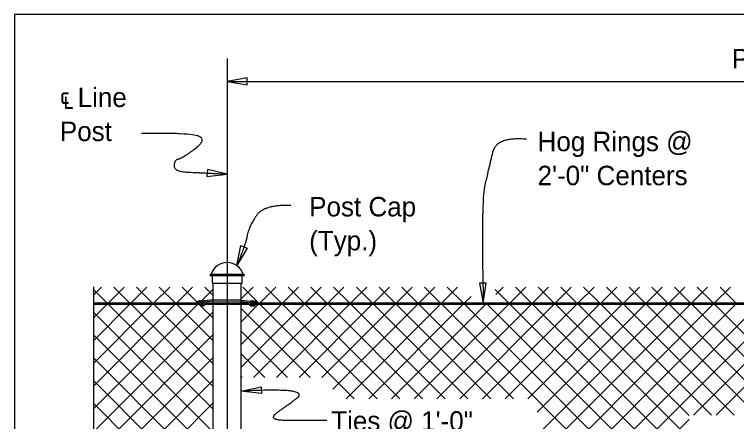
# Model space of a CAD drawing. Extents: x 0 to 72.1, y -7 to 30.
# Drawn here: x 0.02 to 7.5, y 23.8 to 28.01 of the extents above; entities that cross this region are included whole.
import ezdxf

# ---------------------------------------------------------------- set-up
doc = ezdxf.new("R2010")
doc.units = 0
for name, color, linetype in [('ActivePts-ConstElements', 7, 'Continuous'), ('AdhocPoint_dp', 7, 'Continuous'), ('Border', 7, 'Continuous'), ('Patterning', 7, 'Continuous'), ('PlotBorder_dp', 7, 'Continuous'), ('SheetBorder_dp', 7, 'Continuous'), ('TextStructures', 7, 'Continuous')]:
    doc.layers.add(name, color=color, linetype=linetype)

msp = doc.modelspace()

# ---------------------------------------------------------------- linework, layer by layer
at = {"layer": 'ActivePts-ConstElements'}
msp.add_lwpolyline([(0.016, 2.0538), (41.2266, 2.0538), (41.2266, 28.0138), (0.016, 28.0138)], close=True, dxfattribs=at)
at = {"layer": 'AdhocPoint_dp'}
for p, q in [((0.9187, 25.1899), (0.8352, 25.1065)), ((0.9779, 25.0233), (0.8352, 25.1659)), ((1.1544, 25.1899), (0.9877, 25.0233)), ((1.2136, 25.0233), (1.0469, 25.1899)), ((1.3901, 25.1899), (1.2234, 25.0233)), ((1.4493, 25.0233), (1.2826, 25.1899)), ((1.6258, 25.1899), (1.4591, 25.0233)), ((1.685, 25.0233), (1.5183, 25.1899)), ((1.8615, 25.1899), (1.6948, 25.0233)), ((1.9092, 25.0348), (1.754, 25.1899)), ((2.0763, 25.1691), (1.9541, 25.0468)), ((2.0763, 25.1033), (1.9897, 25.1899)), ((2.4906, 25.1899), (2.368, 25.0674)), ((2.5498, 25.0233), (2.3831, 25.1899)), ((2.7263, 25.1899), (2.5596, 25.0233)), ((2.7855, 25.0233), (2.6188, 25.1899)), ((2.962, 25.1899), (2.7953, 25.0233)), ((3.0212, 25.0233), (2.8545, 25.1899)), ((3.1977, 25.1899), (3.031, 25.0233)), ((3.2569, 25.0233), (3.0902, 25.1899)), ((3.4334, 25.1899), (3.2667, 25.0233)), ((3.4926, 25.0233), (3.3259, 25.1899)), ((3.6691, 25.1899), (3.5024, 25.0233)), ((3.7283, 25.0233), (3.5616, 25.1899)), ((3.9048, 25.1899), (3.7381, 25.0233)), ((3.964, 25.0233), (3.7973, 25.1899)), ((4.1405, 25.1899), (3.9738, 25.0233)), ((4.1997, 25.0233), (4.033, 25.1899)), ((4.3762, 25.1899), (4.2095, 25.0233)), ((4.4354, 25.0233), (4.2687, 25.1899)), ((4.6119, 25.1899), (4.4452, 25.0233)), ((4.6711, 25.0233), (4.5044, 25.1899)), ((5.1425, 25.0233), (5.0007, 25.1651)), ((5.0833, 25.1899), (5.0071, 25.1137)), ((5.319, 25.1899), (5.1523, 25.0233)), ((5.3782, 25.0233), (5.2116, 25.1899)), ((5.5547, 25.1899), (5.388, 25.0233)), ((5.6139, 25.0233), (5.4473, 25.1899)), ((5.7904, 25.1899), (5.6237, 25.0233)), ((5.8496, 25.0233), (5.683, 25.1899)), ((6.0261, 25.1899), (5.8594, 25.0233)), ((6.0853, 25.0233), (5.9187, 25.1899)), ((6.2618, 25.1899), (6.0951, 25.0233)), ((6.321, 25.0233), (6.1544, 25.1899)), ((6.4975, 25.1899), (6.3308, 25.0233)), ((6.5567, 25.0233), (6.3901, 25.1899)), ((6.7332, 25.1899), (6.5665, 25.0233)), ((6.7924, 25.0233), (6.6258, 25.1899)), ((6.9689, 25.1899), (6.8022, 25.0233)), ((7.0281, 25.0233), (6.8615, 25.1899)), ((7.2046, 25.1899), (7.0379, 25.0233)), ((7.2638, 25.0233), (7.0972, 25.1899)), ((7.4403, 25.1899), (7.2736, 25.0233)), ((7.4995, 25.0233), (7.3329, 25.1899)), ((4.7518, 25.0941), (4.6809, 25.0233)), ((1.9207, 25.0233), (1.9163, 25.0277)), ((4.9068, 25.0233), (4.9068, 25.0233)), ((1.9158, 25.0085), (0.8352, 23.928)), ((1.6801, 25.0085), (0.8352, 24.1637)), ((1.2087, 25.0085), (0.8352, 24.6351)), ((1.4444, 25.0085), (0.8352, 24.3994)), ((0.973, 25.0085), (0.8352, 24.8708)), ((2.0763, 23.9248), (0.9927, 25.0085)), ((2.0719, 24.165), (1.2284, 25.0085)), ((2.0763, 24.3962), (1.4641, 25.0085)), ((2.0763, 24.6319), (1.6998, 25.0085)), ((2.0763, 24.8676), (1.9469, 24.9971)), ((3.0163, 25.0085), (2.368, 24.3603)), ((2.7806, 25.0085), (2.368, 24.596)), ((2.5449, 25.0085), (2.368, 24.8317)), ((3.0842, 24.2532), (2.368, 24.9694)), ((3.252, 25.0085), (2.4966, 24.2532)), ((3.5404, 24.0327), (2.5645, 25.0085)), ((3.4877, 25.0085), (2.7323, 24.2532)), ((3.7761, 24.0327), (2.8002, 25.0085)), ((3.7234, 25.0085), (2.968, 24.2532)), ((4.0118, 24.0327), (3.0359, 25.0085)), ((3.9591, 25.0085), (3.2037, 24.2532)), ((4.2475, 24.0327), (3.2716, 25.0085)), ((4.1948, 25.0085), (3.319, 24.1328)), ((4.4305, 25.0085), (3.4546, 24.0327)), ((4.4832, 24.0327), (3.5073, 25.0085)), ((4.6662, 25.0085), (3.6903, 24.0327)), ((4.7189, 24.0327), (3.7431, 25.0085)), ((4.9019, 25.0085), (3.926, 24.0327)), ((4.9546, 24.0327), (3.9788, 25.0085)), ((5.1376, 25.0085), (4.1617, 24.0327)), ((5.1903, 24.0327), (4.2145, 25.0085)), ((7.2589, 25.0085), (4.2934, 22.043)), ((5.3733, 25.0085), (4.3974, 24.0327)), ((7.2652, 22.1934), (4.4502, 25.0085)), ((7.4946, 25.0085), (4.5291, 22.043)), ((5.609, 25.0085), (4.6331, 24.0327)), ((7.4194, 22.2749), (4.6859, 25.0085)), ((7.7303, 25.0085), (4.7648, 22.043)), ((5.8447, 25.0085), (4.8688, 24.0327)), ((7.5736, 22.3564), (4.9216, 25.0085)), ((7.966, 25.0085), (5.0005, 22.043)), ((6.0804, 25.0085), (5.1045, 24.0327)), ((7.7279, 22.4379), (5.1573, 25.0085)), ((6.3161, 25.0085), (5.3403, 24.0327)), ((7.0117, 23.3898), (5.393, 25.0085)), ((6.5518, 25.0085), (5.4365, 23.8932)), ((6.7875, 25.0085), (5.4365, 23.6575)), ((7.0232, 25.0085), (5.5838, 23.5691)), ((7.0117, 23.6255), (5.6287, 25.0085)), ((7.0117, 23.8612), (5.8644, 25.0085)), ((7.2437, 23.8649), (6.1001, 25.0085)), ((7.4794, 23.8649), (6.3358, 25.0085)), ((7.7151, 23.8649), (6.5715, 25.0085)), ((7.9508, 23.8649), (6.8072, 25.0085)), ((8.1865, 23.8649), (7.0429, 25.0085)), ((8.2017, 25.0085), (7.057, 23.8638)), ((8.4222, 23.8649), (7.2786, 25.0085)), ((8.4374, 25.0085), (7.2938, 23.8649)), ((2.0763, 24.9334), (0.8352, 23.6923)), ((2.0763, 23.6891), (0.8352, 24.9302)), ((2.8485, 24.2532), (2.368, 24.7337)), ((2.0763, 24.6977), (0.8352, 23.4566)), ((2.0763, 23.4534), (0.8352, 24.6945)), ((2.6128, 24.2532), (2.368, 24.4979)), ((2.0763, 24.462), (0.8142, 23.1998)), ((2.0763, 23.2177), (0.8352, 24.4588)), ((2.3771, 24.2532), (2.368, 24.2622)), ((2.0763, 24.2263), (0.8352, 22.9852)), ((2.0763, 22.982), (0.8352, 24.2231)), ((2.0763, 23.9906), (0.8352, 22.7495)), ((2.0763, 22.7463), (0.8352, 23.9874)), ((7.0117, 23.8185), (5.2362, 22.043))]:
    msp.add_line(p, q, dxfattribs=at)
at = {"layer": 'Border'}
msp.add_line((2.2222, 27.321), (22.2222, 27.321), dxfattribs=at)
for points in [[(2.2223, 27.321), (2.4305, 27.2858), (2.4305, 27.3563)], [(2.2223, 26.36), (2.0163, 26.4066), (2.0124, 26.3362)], [(2.3222, 25.4134), (2.3642, 25.6204), (2.43, 25.595)], [(4.8783, 25.0233), (4.9091, 25.2323), (4.8386, 25.2308)], [(2.3679, 24.1139), (2.5745, 24.1577), (2.5774, 24.0872)]]:
    msp.add_lwpolyline(points, close=True, dxfattribs=at)
msp.add_lwpolyline([(0.8354, 25.192), (0.8354, 23.2357), (0.9387, 23.2357), (0.8354, 23.1907), (0.7321, 23.1457), (0.8354, 23.1457), (0.8354, 22.2521)], dxfattribs=at)
for points in [[(1.3326, 26.7837), (1.8784, 26.7935), (2.0008, 26.7046), (1.7566, 26.5233), (1.6718, 26.505), (1.6718, 26.3871), (1.9498, 26.3749), (2.2221, 26.36)], [(5.3276, 26.7208), (5.0142, 26.7491), (4.9358, 26.4269), (4.8527, 26.0686), (4.8782, 25.0233)], [(2.8807, 26.0339), (2.6059, 26.0467), (2.4461, 25.8164), (2.4125, 25.6291), (2.3221, 25.4134)], [(3.2562, 23.8092), (3.0439, 23.8092), (2.6239, 23.8092), (2.8741, 23.9863), (3.0113, 24.089), (2.8008, 24.1315), (2.368, 24.1138)]]:
    msp.add_open_spline(points, degree=2, dxfattribs=at)
at = {"layer": 'Patterning'}
for p, q in [((2.368, 25.0233), (2.0763, 25.0233)), ((2.368, 25.0085), (2.0763, 25.0085))]:
    msp.add_line(p, q, dxfattribs=at)
at = {"layer": 'PlotBorder_dp'}
for p, q in [((2.3947, 25.3219), (2.05, 25.3219)), ((2.05, 25.3097), (2.3947, 25.3097)), ((2.0682, 25.2299), (2.0682, 25.3097)), ((2.3763, 25.2299), (2.3763, 25.3097)), ((2.0682, 25.2299), (2.3763, 25.2299)), ((2.0763, 19.5847), (2.0763, 25.2299)), ((2.368, 19.5847), (2.368, 25.2299)), ((1.9019, 25.0233), (0.8353, 25.0233)), ((1.9256, 25.0233), (1.9103, 25.0233)), ((2.0768, 25.0576), (1.9825, 25.0465)), ((2.0768, 25.043), (1.9847, 25.0336)), ((2.0763, 25.0233), (1.9959, 25.0233)), ((2.368, 25.0559), (2.0768, 25.0576)), ((2.368, 25.0414), (2.0768, 25.043)), ((2.368, 25.0559), (2.4629, 25.0448)), ((2.368, 25.0414), (2.4606, 25.0318)), ((2.4502, 25.0233), (2.368, 25.0233)), ((2.5332, 25.0233), (2.5201, 25.0233)), ((11.939, 25.0233), (2.5432, 25.0233)), ((1.9305, 25.0085), (0.8353, 25.0085)), ((2.0763, 25.0085), (1.9933, 25.0085)), ((2.4516, 25.0085), (2.368, 25.0085)), ((11.9403, 25.0085), (2.5165, 25.0085))]:
    msp.add_line(p, q, dxfattribs=at)
for centre, start, end in [((2.05, 25.3156), 91.1647, 268.8353), ((2.3944, 25.3156), 271.1647, 88.8353)]:
    msp.add_arc(centre, 0.00613, start, end, dxfattribs=at)
for centre, major_axis, ratio, start_param, end_param in [((2.2215, 25.2808), (-0.1711, 0), 0.957868, 3.394611, 6.030583), ((1.9369, 25.0108), (0.0373, 0), 0.957868, 1.486836, 3.108042), ((1.958, 24.9711), (-0.0724, 0), 0.957868, 5.162149, 5.652106), ((1.9505, 25.0227), (-0.0249, 0), 0.957868, 6.009018, 7.089857), ((1.9494, 25.0253), (0.023, 0), 0.957868, 1.29026, 2.970541), ((1.9681, 25.0199), (0.0295, 0), 0.957868, 1.220941, 4.039556), ((1.9816, 25.0217), (-0.0303, -0.0108), 0.724765, 4.35367, 6.324556), ((1.9715, 25.0131), (0.0206, -0.0021), 0.798607, 3.333154, 5.220153), ((1.9783, 25.0176), (-0.0139, 0), 0.957868, 5.22362, 6.905413), ((1.9726, 25.0152), (-0.00795, 0), 0.957868, 6.140374, 9.314262), ((1.9866, 25.0087), (-0.0259, 0), 0.957868, 4.777514, 5.62749), ((1.9709, 25.021), (0.0119, 0), 0.957868, 5.725876, 7.416677), ((1.9709, 25.021), (0.0119, 0), 0.957868, 5.639684, 5.723117), ((1.9711, 25.0198), (0.0251, 0), 0.957868, 5.531357, 6.227833), ((1.9711, 25.0198), (0.0251, 0), 0.957868, 0.407687, 0.609214), ((2.4746, 25.018), (-0.0251, 0), 0.957868, 0.055352, 0.751829), ((2.4746, 25.018), (-0.0251, 0), 0.957868, 5.673972, 5.875498), ((2.4591, 25.007), (0.0259, 0), 0.957868, 0.655696, 1.505671), ((2.4642, 25.0199), (0.0303, -0.0108), 0.724765, 6.241815, 8.212701), ((2.4749, 25.0192), (-0.0119, 0), 0.957868, 5.149694, 6.840495), ((2.4749, 25.0192), (-0.0119, 0), 0.957868, 0.560069, 0.643501), ((2.4732, 25.0134), (0.00795, 0), 0.957868, 3.252108, 6.425997), ((2.4777, 25.0181), (-0.0295, 0), 0.957868, 2.243629, 5.062245), ((2.4675, 25.0158), (0.0139, 0), 0.957868, 5.660958, 7.342751), ((2.4964, 25.0235), (-0.023, 0), 0.957868, 3.312645, 4.992926), ((2.5089, 25.009), (-0.0373, 0), 0.957868, 3.175144, 4.79635), ((2.4953, 25.021), (0.0249, 0), 0.957868, 5.476514, 6.557353), ((2.4878, 24.9693), (0.0724, 0), 0.957868, 0.631079, 1.121037), ((1.9519, 25.0187), (0.0231, 0), 0.957868, 3.779554, 4.879821), ((1.958, 25.0131), (0.0206, -0.0021), 0.798607, 4.32653, 5.220153), ((1.9641, 25.0318), (0.0391, 0), 0.957868, 5.082588, 5.41974), ((2.4817, 25.03), (-0.0391, 0), 0.957868, 0.863445, 1.200597), ((2.4743, 25.0113), (-0.0206, -0.0021), 0.798607, 1.063032, 2.950031), ((2.4878, 25.0113), (-0.0206, -0.0021), 0.798607, 1.063032, 1.956656), ((2.4939, 25.017), (-0.0231, 0), 0.957868, 1.403365, 2.503632)]:
    msp.add_ellipse(centre, major_axis=major_axis, ratio=ratio, start_param=start_param, end_param=end_param, dxfattribs=at)
at = {"layer": 'SheetBorder_dp'}
msp.add_line((2.2222, 27.5581), (2.2222, 16.7178), dxfattribs=at)

# ---------------------------------------------------------------- texts
at = {"layer": 'Border'}
for s, p in [('℄ Line ', (0.4872, 27.0548)), ('Post', (0.4872, 26.7028)), ('Hog Rings @ ', (5.441, 26.5975)), ('2\'-0" Centers', (5.441, 26.2455)), ('Post Cap ', (3.0726, 25.9221)), ('(Typ.)', (3.0726, 25.5701))]:
    msp.add_text(s, height=0.2016, dxfattribs=at).set_placement(p)
at = {"layer": 'TextStructures'}
for s, p in [('Pull Post Assembly (required at maximum intervals of 500\'-0")', (7.4543, 27.4558)), ('Ties @ 1\'-0" ', (3.301, 23.7032))]:
    msp.add_text(s, height=0.2016, dxfattribs=at).set_placement(p)

doc.saveas('drawing.dxf')
